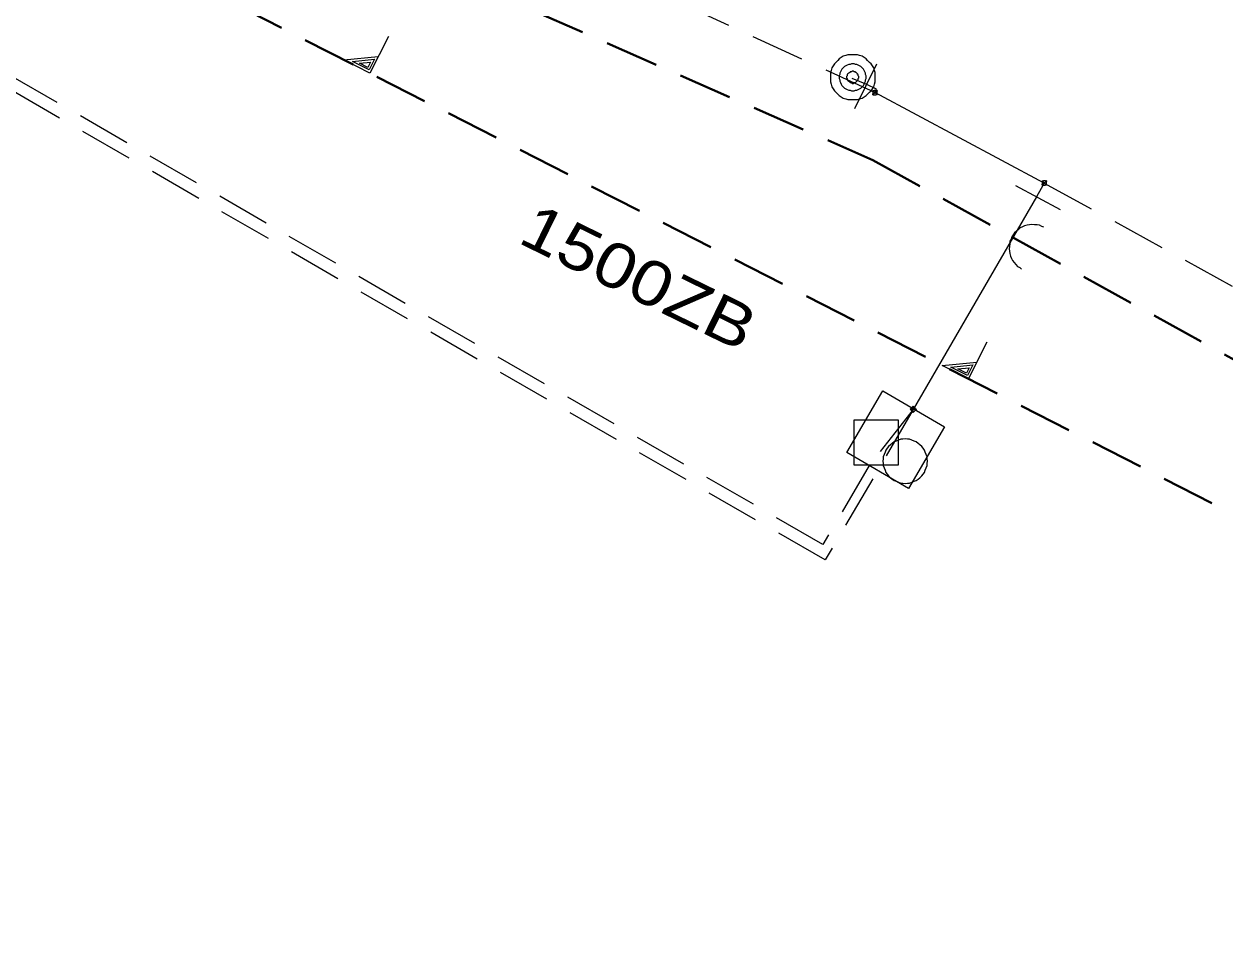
# Model space of a CAD drawing. Extents: x -740851 to -738888, y -1041382 to -1040235.
# Drawn here: x -739788.69 to -739761.8, y -1040534.07 to -1040513.53 of the extents above; entities that cross this region are included whole.
import ezdxf

# ---------------------------------------------------------------- set-up
doc = ezdxf.new("R2010")
doc.units = 0
doc.header["$LTSCALE"] = 0.4
doc.linetypes.add('MEDIUM_DASHED', pattern=[4.5, 3, -1.5])
for name, color, linetype, lineweight in [('18', 7, 'Continuous', 13), ('38', 7, 'Continuous', 13), ('39', 7, 'MEDIUM_DASHED', 13), ('8', 7, 'Continuous', 13)]:
    doc.layers.add(name, color=color, linetype=linetype, lineweight=lineweight)

msp = doc.modelspace()

# ---------------------------------------------------------------- linework, layer by layer
at = {"layer": '18', "linetype": 'MEDIUM_DASHED', "lineweight": 40}
msp.add_line((-739746.06, -1040532.45), (-739799.87, -1040504.96), dxfattribs=at)
at = {"layer": '18'}
for points in [[(-739780.53, -1040513.808), (-739780.947, -1040514.625), (-739781.53, -1040514.327), (-739780.759, -1040514.256)], [(-739780.844, -1040514.316), (-739780.965, -1040514.554), (-739781.338, -1040514.364), (-739780.84, -1040514.318)], [(-739780.931, -1040514.38), (-739780.991, -1040514.499), (-739781.182, -1040514.401), (-739780.927, -1040514.382)], [(-739767.128, -1040520.655), (-739767.545, -1040521.471), (-739768.128, -1040521.174), (-739767.357, -1040521.103)], [(-739767.442, -1040521.163), (-739767.563, -1040521.401), (-739767.935, -1040521.211), (-739767.438, -1040521.165)], [(-739767.528, -1040521.227), (-739767.589, -1040521.346), (-739767.78, -1040521.248), (-739767.524, -1040521.229)]]:
    msp.add_lwpolyline(points, dxfattribs=at)
at = {"layer": '38'}
for p, q in [((-739765.844, -1040517.089), (-739766.02, -1040517.4)), ((-739766.02, -1040517.4), (-739768.78, -1040522.16))]:
    msp.add_line(p, q, dxfattribs=at)
at = {"layer": '38', "linetype": 'MEDIUM_DASHED'}
msp.add_lwpolyline([(-739768.78, -1040522.16), (-739769.767, -1040523.416), (-739770.8, -1040525.186), (-739789.007, -1040514.675), (-739802.146, -1040514.35), (-739881.581, -1040591.514)], dxfattribs=at)
at = {"layer": '39'}
msp.add_lwpolyline([(-739768.78, -1040522.16), (-739770.749, -1040525.533), (-739789.095, -1040514.942), (-739801.973, -1040514.623), (-739881.335, -1040591.716)], dxfattribs=at)
at = {"layer": '8'}
for p, q in [((-739770.088, -1040515.42), (-739769.591, -1040514.42)), ((-739769.685, -1040515.114), (-739769.585, -1040515.014)), ((-739769.685, -1040515.014), (-739769.585, -1040515.114)), ((-739769.685, -1040515.014), (-739769.685, -1040515.034)), ((-739769.685, -1040515.014), (-739769.665, -1040515.014)), ((-739769.685, -1040515.114), (-739769.685, -1040515.094)), ((-739769.685, -1040515.114), (-739769.665, -1040515.114)), ((-739769.585, -1040515.014), (-739769.605, -1040515.014)), ((-739769.585, -1040515.114), (-739769.605, -1040515.114)), ((-739769.585, -1040515.014), (-739769.585, -1040515.034)), ((-739769.585, -1040515.114), (-739769.585, -1040515.094)), ((-739765.48, -1040517.689), (-739766.48, -1040517.154)), ((-739765.893, -1040517.138), (-739765.793, -1040517.038)), ((-739765.893, -1040517.038), (-739765.793, -1040517.138)), ((-739765.893, -1040517.038), (-739765.893, -1040517.058)), ((-739765.893, -1040517.038), (-739765.873, -1040517.038)), ((-739765.893, -1040517.138), (-739765.893, -1040517.118)), ((-739765.893, -1040517.138), (-739765.873, -1040517.138)), ((-739765.793, -1040517.038), (-739765.813, -1040517.038)), ((-739765.793, -1040517.138), (-739765.813, -1040517.138)), ((-739765.793, -1040517.038), (-739765.793, -1040517.058)), ((-739765.793, -1040517.138), (-739765.793, -1040517.118)), ((-739768.851, -1040522.157), (-739768.836, -1040522.143)), ((-739768.851, -1040522.157), (-739768.709, -1040522.16)), ((-739768.851, -1040522.157), (-739768.837, -1040522.172)), ((-739768.781, -1040522.229), (-739768.795, -1040522.215)), ((-739768.779, -1040522.088), (-739768.793, -1040522.102)), ((-739768.781, -1040522.229), (-739768.779, -1040522.088)), ((-739768.781, -1040522.229), (-739768.767, -1040522.215)), ((-739768.779, -1040522.088), (-739768.765, -1040522.102)), ((-739768.709, -1040522.16), (-739768.724, -1040522.174)), ((-739768.709, -1040522.16), (-739768.723, -1040522.145))]:
    msp.add_line(p, q, dxfattribs=at)
at = {"layer": '8', "lineweight": 25}
msp.add_line((-739765.844, -1040517.089), (-739769.636, -1040515.065), dxfattribs=at)
at = {"layer": '8', "linetype": 'MEDIUM_DASHED', "lineweight": 25}
for points in [[(-739769.636, -1040515.065), (-739798.96, -1040501.6), (-739806.89, -1040499.33), (-739808.75, -1040483.96), (-739809.48, -1040483.712)], [(-739765.844, -1040517.089), (-739747.16, -1040527.33), (-739744.46, -1040529.01)]]:
    msp.add_lwpolyline(points, dxfattribs=at)
at = {"layer": '8', "linetype": 'MEDIUM_DASHED', "lineweight": 40}
msp.add_lwpolyline([(-739800.406, -1040510.509), (-739783.874, -1040510.33), (-739769.682, -1040516.575), (-739747.937, -1040528.604), (-739744.345, -1040531.012), (-739722.292, -1040550.654), (-739710.435, -1040562.012), (-739703.68, -1040568.1)], dxfattribs=at)
at = {"layer": '8'}
for points in [[(-739769.634, -1040514.719), (-739769.634, -1040514.674), (-739769.634, -1040514.613), (-739769.65, -1040514.568), (-739769.665, -1040514.507), (-739769.695, -1040514.462), (-739769.725, -1040514.416), (-739769.756, -1040514.386), (-739769.801, -1040514.341), (-739769.831, -1040514.31), (-739769.877, -1040514.28), (-739769.922, -1040514.25), (-739769.983, -1040514.235), (-739770.028, -1040514.219), (-739770.089, -1040514.219), (-739770.134, -1040514.219), (-739770.195, -1040514.219), (-739770.241, -1040514.219), (-739770.286, -1040514.235), (-739770.347, -1040514.25), (-739770.392, -1040514.28), (-739770.437, -1040514.31), (-739770.468, -1040514.341), (-739770.513, -1040514.386), (-739770.544, -1040514.416), (-739770.574, -1040514.462), (-739770.604, -1040514.507), (-739770.619, -1040514.568), (-739770.634, -1040514.613), (-739770.634, -1040514.674), (-739770.634, -1040514.719), (-739770.634, -1040514.78), (-739770.634, -1040514.825), (-739770.619, -1040514.871), (-739770.604, -1040514.932), (-739770.574, -1040514.977), (-739770.544, -1040515.022), (-739770.513, -1040515.053), (-739770.468, -1040515.098), (-739770.437, -1040515.128), (-739770.392, -1040515.159), (-739770.347, -1040515.189), (-739770.286, -1040515.204), (-739770.241, -1040515.219), (-739770.195, -1040515.219), (-739770.134, -1040515.219), (-739770.089, -1040515.219), (-739770.028, -1040515.219), (-739769.983, -1040515.204), (-739769.922, -1040515.189), (-739769.877, -1040515.159), (-739769.831, -1040515.128), (-739769.801, -1040515.098), (-739769.756, -1040515.053), (-739769.725, -1040515.022), (-739769.695, -1040514.977), (-739769.665, -1040514.932), (-739769.65, -1040514.871), (-739769.634, -1040514.825), (-739769.634, -1040514.78)], [(-739769.831, -1040514.719), (-739769.831, -1040514.689), (-739769.847, -1040514.659), (-739769.847, -1040514.628), (-739769.862, -1040514.598), (-739769.877, -1040514.568), (-739769.892, -1040514.538), (-739769.907, -1040514.522), (-739769.937, -1040514.492), (-739769.953, -1040514.477), (-739769.983, -1040514.462), (-739770.013, -1040514.447), (-739770.044, -1040514.432), (-739770.074, -1040514.432), (-739770.104, -1040514.416), (-739770.134, -1040514.416), (-739770.165, -1040514.416), (-739770.195, -1040514.432), (-739770.225, -1040514.432), (-739770.256, -1040514.447), (-739770.286, -1040514.462), (-739770.316, -1040514.477), (-739770.331, -1040514.492), (-739770.362, -1040514.522), (-739770.377, -1040514.538), (-739770.392, -1040514.568), (-739770.407, -1040514.598), (-739770.422, -1040514.628), (-739770.422, -1040514.659), (-739770.437, -1040514.689), (-739770.437, -1040514.719), (-739770.437, -1040514.75), (-739770.422, -1040514.78), (-739770.422, -1040514.81), (-739770.407, -1040514.841), (-739770.392, -1040514.871), (-739770.377, -1040514.901), (-739770.362, -1040514.916), (-739770.331, -1040514.947), (-739770.316, -1040514.962), (-739770.286, -1040514.977), (-739770.256, -1040514.992), (-739770.225, -1040515.007), (-739770.195, -1040515.007), (-739770.165, -1040515.022), (-739770.134, -1040515.022), (-739770.104, -1040515.022), (-739770.074, -1040515.007), (-739770.044, -1040515.007), (-739770.013, -1040514.992), (-739769.983, -1040514.977), (-739769.953, -1040514.962), (-739769.937, -1040514.947), (-739769.907, -1040514.916), (-739769.892, -1040514.901), (-739769.877, -1040514.871), (-739769.862, -1040514.841), (-739769.847, -1040514.81), (-739769.847, -1040514.78), (-739769.831, -1040514.75)], [(-739769.998, -1040514.719), (-739769.998, -1040514.704), (-739770.013, -1040514.689), (-739770.013, -1040514.674), (-739770.013, -1040514.659), (-739770.028, -1040514.659), (-739770.028, -1040514.644), (-739770.044, -1040514.628), (-739770.059, -1040514.613), (-739770.074, -1040514.613), (-739770.074, -1040514.598), (-739770.089, -1040514.598), (-739770.104, -1040514.598), (-739770.119, -1040514.583), (-739770.134, -1040514.583), (-739770.15, -1040514.583), (-739770.165, -1040514.598), (-739770.18, -1040514.598), (-739770.195, -1040514.598), (-739770.195, -1040514.613), (-739770.21, -1040514.613), (-739770.225, -1040514.628), (-739770.241, -1040514.644), (-739770.256, -1040514.659), (-739770.256, -1040514.674), (-739770.256, -1040514.689), (-739770.271, -1040514.704), (-739770.271, -1040514.719), (-739770.271, -1040514.735), (-739770.256, -1040514.75), (-739770.256, -1040514.765), (-739770.256, -1040514.78), (-739770.241, -1040514.795), (-739770.225, -1040514.81), (-739770.21, -1040514.825), (-739770.195, -1040514.841), (-739770.18, -1040514.841), (-739770.165, -1040514.841), (-739770.15, -1040514.856), (-739770.134, -1040514.856), (-739770.119, -1040514.856), (-739770.104, -1040514.841), (-739770.089, -1040514.841), (-739770.074, -1040514.841), (-739770.059, -1040514.825), (-739770.044, -1040514.81), (-739770.028, -1040514.795), (-739770.028, -1040514.78), (-739770.013, -1040514.78), (-739770.013, -1040514.765), (-739770.013, -1040514.75), (-739769.998, -1040514.735)], [(-739769.585, -1040515.064), (-739769.585, -1040515.059), (-739769.586, -1040515.054), (-739769.587, -1040515.049), (-739769.589, -1040515.044), (-739769.592, -1040515.039), (-739769.595, -1040515.035), (-739769.598, -1040515.031), (-739769.602, -1040515.027), (-739769.606, -1040515.024), (-739769.61, -1040515.021), (-739769.615, -1040515.018), (-739769.62, -1040515.016), (-739769.625, -1040515.015), (-739769.63, -1040515.014), (-739769.635, -1040515.014), (-739769.64, -1040515.014), (-739769.645, -1040515.015), (-739769.65, -1040515.016), (-739769.655, -1040515.018), (-739769.66, -1040515.021), (-739769.664, -1040515.024), (-739769.668, -1040515.027), (-739769.672, -1040515.031), (-739769.675, -1040515.035), (-739769.678, -1040515.039), (-739769.681, -1040515.044), (-739769.683, -1040515.049), (-739769.684, -1040515.054), (-739769.685, -1040515.059), (-739769.685, -1040515.064), (-739769.685, -1040515.069), (-739769.684, -1040515.074), (-739769.683, -1040515.079), (-739769.681, -1040515.084), (-739769.678, -1040515.089), (-739769.675, -1040515.093), (-739769.672, -1040515.097), (-739769.668, -1040515.101), (-739769.664, -1040515.104), (-739769.66, -1040515.107), (-739769.655, -1040515.11), (-739769.65, -1040515.112), (-739769.645, -1040515.113), (-739769.64, -1040515.114), (-739769.635, -1040515.114), (-739769.63, -1040515.114), (-739769.625, -1040515.113), (-739769.62, -1040515.112), (-739769.615, -1040515.11), (-739769.61, -1040515.107), (-739769.606, -1040515.104), (-739769.602, -1040515.101), (-739769.598, -1040515.097), (-739769.595, -1040515.093), (-739769.592, -1040515.089), (-739769.589, -1040515.084), (-739769.587, -1040515.079), (-739769.586, -1040515.074), (-739769.585, -1040515.069)], [(-739765.793, -1040517.088), (-739765.793, -1040517.083), (-739765.794, -1040517.078), (-739765.795, -1040517.073), (-739765.797, -1040517.068), (-739765.8, -1040517.063), (-739765.803, -1040517.059), (-739765.806, -1040517.055), (-739765.81, -1040517.051), (-739765.814, -1040517.048), (-739765.818, -1040517.045), (-739765.823, -1040517.042), (-739765.828, -1040517.04), (-739765.833, -1040517.039), (-739765.838, -1040517.038), (-739765.843, -1040517.038), (-739765.848, -1040517.038), (-739765.853, -1040517.039), (-739765.858, -1040517.04), (-739765.863, -1040517.042), (-739765.868, -1040517.045), (-739765.872, -1040517.048), (-739765.876, -1040517.051), (-739765.88, -1040517.055), (-739765.883, -1040517.059), (-739765.886, -1040517.063), (-739765.889, -1040517.068), (-739765.891, -1040517.073), (-739765.892, -1040517.078), (-739765.893, -1040517.083), (-739765.893, -1040517.088), (-739765.893, -1040517.093), (-739765.892, -1040517.098), (-739765.891, -1040517.103), (-739765.889, -1040517.108), (-739765.886, -1040517.113), (-739765.883, -1040517.117), (-739765.88, -1040517.121), (-739765.876, -1040517.125), (-739765.872, -1040517.128), (-739765.868, -1040517.131), (-739765.863, -1040517.134), (-739765.858, -1040517.136), (-739765.853, -1040517.137), (-739765.848, -1040517.138), (-739765.843, -1040517.138), (-739765.838, -1040517.138), (-739765.833, -1040517.137), (-739765.828, -1040517.136), (-739765.823, -1040517.134), (-739765.818, -1040517.131), (-739765.814, -1040517.128), (-739765.81, -1040517.125), (-739765.806, -1040517.121), (-739765.803, -1040517.117), (-739765.8, -1040517.113), (-739765.797, -1040517.108), (-739765.795, -1040517.103), (-739765.794, -1040517.098), (-739765.793, -1040517.093)], [(-739768.887, -1040523.93), (-739770.269, -1040523.124), (-739769.462, -1040521.742), (-739768.08, -1040522.548)], [(-739768.744, -1040522.124), (-739768.747, -1040522.12), (-739768.752, -1040522.117), (-739768.756, -1040522.114), (-739768.761, -1040522.112), (-739768.766, -1040522.111), (-739768.771, -1040522.11), (-739768.776, -1040522.109), (-739768.782, -1040522.109), (-739768.787, -1040522.11), (-739768.792, -1040522.11), (-739768.798, -1040522.112), (-739768.803, -1040522.114), (-739768.807, -1040522.116), (-739768.811, -1040522.119), (-739768.815, -1040522.123), (-739768.818, -1040522.126), (-739768.821, -1040522.13), (-739768.824, -1040522.134), (-739768.826, -1040522.139), (-739768.828, -1040522.145), (-739768.829, -1040522.15), (-739768.829, -1040522.155), (-739768.83, -1040522.161), (-739768.829, -1040522.166), (-739768.828, -1040522.17), (-739768.827, -1040522.176), (-739768.825, -1040522.181), (-739768.822, -1040522.185), (-739768.819, -1040522.19), (-739768.816, -1040522.193), (-739768.812, -1040522.197), (-739768.808, -1040522.2), (-739768.804, -1040522.203), (-739768.799, -1040522.205), (-739768.794, -1040522.206), (-739768.789, -1040522.207), (-739768.784, -1040522.208), (-739768.778, -1040522.208), (-739768.773, -1040522.208), (-739768.768, -1040522.207), (-739768.762, -1040522.206), (-739768.757, -1040522.204), (-739768.753, -1040522.201), (-739768.749, -1040522.198), (-739768.745, -1040522.195), (-739768.742, -1040522.191), (-739768.739, -1040522.187), (-739768.736, -1040522.183), (-739768.734, -1040522.178), (-739768.732, -1040522.172), (-739768.731, -1040522.167), (-739768.731, -1040522.162), (-739768.73, -1040522.157), (-739768.731, -1040522.152), (-739768.732, -1040522.147), (-739768.733, -1040522.141), (-739768.735, -1040522.136), (-739768.738, -1040522.132), (-739768.741, -1040522.127)], [(-739770.108, -1040523.398), (-739769.108, -1040523.398), (-739769.108, -1040522.398), (-739770.108, -1040522.398)], [(-739768.46, -1040523.32), (-739768.47, -1040523.27), (-739768.47, -1040523.22), (-739768.49, -1040523.17), (-739768.51, -1040523.12), (-739768.53, -1040523.07), (-739768.56, -1040523.03), (-739768.59, -1040522.99), (-739768.63, -1040522.95), (-739768.67, -1040522.92), (-739768.71, -1040522.89), (-739768.76, -1040522.87), (-739768.81, -1040522.85), (-739768.86, -1040522.83), (-739768.91, -1040522.83), (-739768.96, -1040522.82), (-739769.01, -1040522.83), (-739769.06, -1040522.83), (-739769.11, -1040522.85), (-739769.16, -1040522.87), (-739769.21, -1040522.89), (-739769.25, -1040522.92), (-739769.29, -1040522.95), (-739769.33, -1040522.99), (-739769.36, -1040523.03), (-739769.39, -1040523.07), (-739769.41, -1040523.12), (-739769.43, -1040523.17), (-739769.45, -1040523.22), (-739769.45, -1040523.27), (-739769.46, -1040523.32), (-739769.45, -1040523.37), (-739769.45, -1040523.42), (-739769.43, -1040523.47), (-739769.41, -1040523.52), (-739769.39, -1040523.57), (-739769.36, -1040523.61), (-739769.33, -1040523.65), (-739769.29, -1040523.69), (-739769.25, -1040523.72), (-739769.21, -1040523.75), (-739769.16, -1040523.77), (-739769.11, -1040523.79), (-739769.06, -1040523.81), (-739769.01, -1040523.81), (-739768.96, -1040523.82), (-739768.91, -1040523.81), (-739768.86, -1040523.81), (-739768.81, -1040523.79), (-739768.76, -1040523.77), (-739768.71, -1040523.75), (-739768.67, -1040523.72), (-739768.63, -1040523.69), (-739768.59, -1040523.65), (-739768.56, -1040523.61), (-739768.53, -1040523.57), (-739768.51, -1040523.52), (-739768.49, -1040523.47), (-739768.47, -1040523.42), (-739768.47, -1040523.37)]]:
    msp.add_lwpolyline(points, close=True, dxfattribs=at)
at = {"layer": '8', "lineweight": 25}
msp.add_lwpolyline([(-739769.636, -1040515.065), (-739769.605, -1040514.987), (-739769.82, -1040514.88), (-739770.15, -1040514.75)], dxfattribs=at)
at = {"layer": '8'}
msp.add_lwpolyline([(-739765.851, -1040518.077), (-739765.903, -1040518.061), (-739765.95, -1040518.036), (-739766.007, -1040518.029), (-739766.064, -1040518.023), (-739766.121, -1040518.017), (-739766.174, -1040518.025), (-739766.226, -1040518.033), (-739766.284, -1040518.05), (-739766.332, -1040518.073), (-739766.381, -1040518.095), (-739766.425, -1040518.132), (-739766.469, -1040518.169), (-739766.513, -1040518.206), (-739766.538, -1040518.253), (-739766.572, -1040518.295), (-739766.588, -1040518.347), (-739766.613, -1040518.394), (-739766.619, -1040518.451), (-739766.626, -1040518.508), (-739766.632, -1040518.566), (-739766.624, -1040518.618), (-739766.616, -1040518.671), (-739766.598, -1040518.729), (-739766.576, -1040518.777), (-739766.553, -1040518.825), (-739766.516, -1040518.869), (-739766.479, -1040518.913), (-739766.442, -1040518.957), (-739766.395, -1040518.982), (-739766.353, -1040519.017)], dxfattribs=at)

# ---------------------------------------------------------------- texts
at = {"layer": '18', "width": 1.2}
msp.add_text('1500ZB', height=1, rotation=333.939, dxfattribs=at).set_placement((-739777.665, -1040518.41))

doc.saveas('drawing.dxf')
